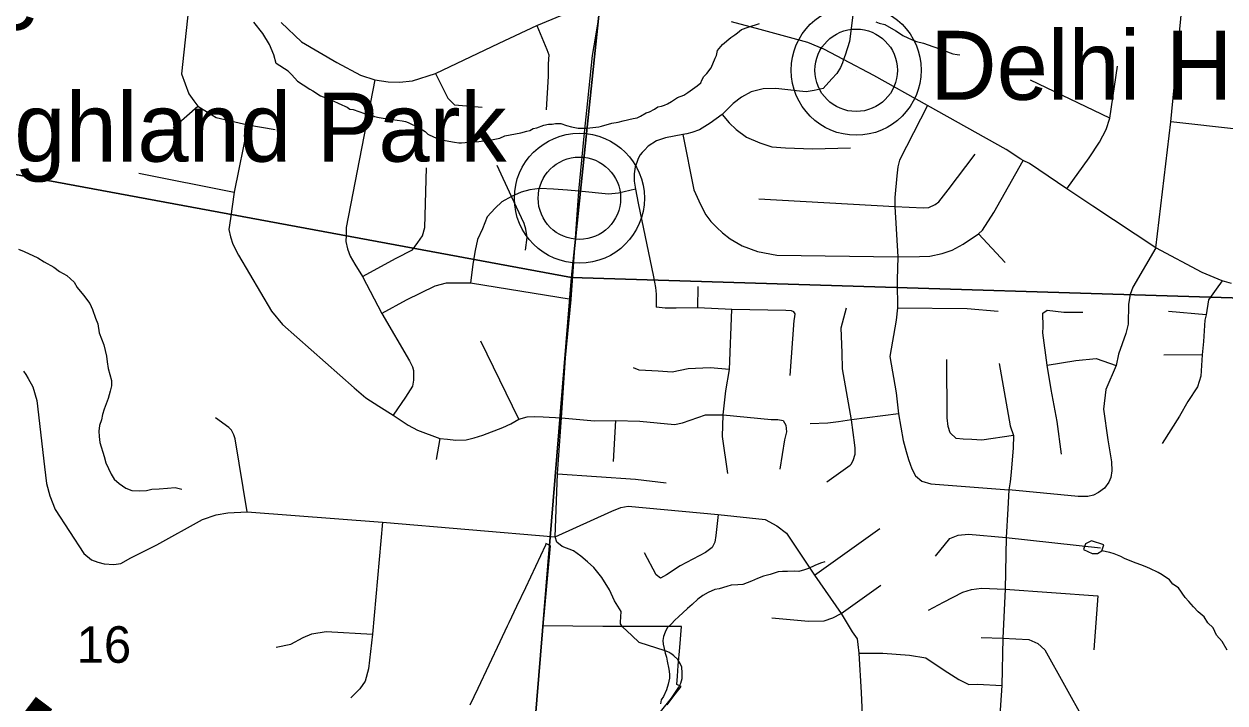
# Model space of a CAD drawing. Extents: x 0 to 43.4, y -8.1 to 22.
# Drawn here: x 6.917 to 8.292, y 14.72 to 15.497 of the extents above; entities that cross this region are included whole.
import ezdxf

# ---------------------------------------------------------------- set-up
doc = ezdxf.new("R2010")
doc.units = 0
for name, color, linetype in [('GM_X_Corporation', 7, 'Continuous'), ('GM_X_County_Road', 7, 'Continuous'), ('GM_X_County_Text', 7, 'Continuous'), ('GM_X_Minor_River', 7, 'Continuous'), ('GM_X_Section_Text', 7, 'Continuous'), ('GM_X_Township_Road', 7, 'Continuous'), ('GM_X_Unincorporated', 7, 'Continuous'), ('GM_X_Unincorporated_Location', 7, 'Continuous'), ('GM_X_Unincorporated_Text', 7, 'Continuous')]:
    doc.layers.add(name, color=color, linetype=linetype)

msp = doc.modelspace()

# ---------------------------------------------------------------- linework, layer by layer
at = {"layer": 'GM_X_Corporation'}
for points in [[(7.6501, 16.228), (7.5438, 15.2065), (6.5194, 15.3962), (6.6267, 16.4119)], [(8.6363, 16.199), (8.5356, 15.1762), (7.5438, 15.2065), (7.6501, 16.228)]]:
    msp.add_lwpolyline(points, close=True, dxfattribs=at)
for points in [[(6.5319, 14.7095), (6.5179, 14.7231), (6.5071, 14.7339), (6.4952, 14.7437), (6.48, 14.7554), (6.4748, 14.7597), (6.4674, 14.7675), (6.4608, 14.776), (6.4541, 14.7814), (6.5194, 15.3962), (7.5438, 15.2065), (7.4624, 14.2166)], [(7.4624, 14.2166), (7.5438, 15.2065), (8.5356, 15.1762), (8.4333, 14.2338)], [(7.6535, 14.7176), (7.6626, 14.7296), (7.6694, 14.7386), (7.6643, 14.7409), (7.6651, 14.7502), (7.6661, 14.7626), (7.6677, 14.7832), (7.6696, 14.807), (7.6426, 14.8071), (7.6251, 14.8073), (7.6212, 14.8072), (7.6046, 14.8073), (7.5905, 14.8073), (7.5867, 14.8073), (7.5797, 14.8073), (7.5452, 14.8076), (7.5113, 14.808), (7.5128, 14.8238), (7.5197, 14.8995), (7.5173, 14.9006), (7.5143, 14.9021), (7.5141, 14.9004), (7.491, 14.8516), (7.4809, 14.8302), (7.472, 14.8114), (7.4703, 14.8077), (7.4618, 14.7897), (7.4364, 14.7361), (7.4274, 14.717)]]:
    msp.add_lwpolyline(points, dxfattribs=at)
at = {"layer": 'GM_X_County_Road'}
msp.add_line((7.5696, 15.4718), (7.579, 15.5267), dxfattribs=at)
for points in [[(8.2129, 15.2407), (8.2301, 15.3849), (8.2507, 15.5974)], [(7.2112, 15.4986), (7.2347, 15.4766), (7.2749, 15.4527), (7.3022, 15.4383), (7.3186, 15.433), (7.334, 15.4307), (7.3468, 15.4303), (7.3616, 15.4317), (7.3881, 15.4404), (7.461, 15.475), (7.5042, 15.4951), (7.5327, 15.5069)], [(8.2993, 15.2), (8.2887, 15.203), (8.266, 15.2125), (8.2129, 15.2407), (8.1406, 15.2884), (8.1111, 15.3081), (8.0681, 15.337), (8.0609, 15.3408), (8.0584, 15.3421), (8.0413, 15.3532), (7.9514, 15.4035), (7.8898, 15.438), (7.8553, 15.4561), (7.8327, 15.468), (7.8263, 15.4708), (7.8143, 15.4757), (7.7598, 15.4907), (7.7271, 15.4992)], [(7.5613, 15.398), (7.5677, 15.4608), (7.5696, 15.4718)], [(7.5251, 14.9099), (7.5277, 14.9821), (7.5323, 15.0459), (7.537, 15.1149), (7.5435, 15.1815), (7.5523, 15.3057), (7.5583, 15.3686), (7.5598, 15.3832), (7.5613, 15.398)], [(7.5998, 14.8123), (7.6008, 14.8243), (7.593, 14.8364), (7.5873, 14.8492), (7.5786, 14.8632), (7.5694, 14.8746), (7.5622, 14.8812), (7.5544, 14.8878), (7.5461, 14.8937), (7.5332, 14.8986), (7.5268, 14.9037), (7.5251, 14.9099)], [(7.6568, 14.7767), (7.656, 14.7773), (7.6512, 14.7792), (7.6214, 14.7888), (7.6129, 14.7967), (7.6021, 14.8068), (7.5997, 14.8103), (7.5998, 14.8123)], [(7.6457, 14.7095), (7.6584, 14.7252), (7.6667, 14.7379), (7.6688, 14.7424), (7.6704, 14.7477), (7.6706, 14.7543), (7.67, 14.7606), (7.6683, 14.7649), (7.6656, 14.7694), (7.6611, 14.7736), (7.6586, 14.7755), (7.6568, 14.7767)]]:
    msp.add_lwpolyline(points, dxfattribs=at)
at = {"layer": 'GM_X_Minor_River'}
for points in [[(7.2194, 15.4427), (7.2056, 15.4516), (7.2028, 15.4615), (7.1978, 15.4734), (7.1905, 15.4861), (7.1802, 15.4989)], [(7.2194, 15.4427), (7.2234, 15.4387), (7.2301, 15.4313), (7.2364, 15.4273), (7.2443, 15.4222), (7.2477, 15.4205), (7.2563, 15.4146), (7.2676, 15.4105), (7.2807, 15.4044), (7.2841, 15.4028), (7.2871, 15.4015), (7.2901, 15.3995), (7.2939, 15.3991), (7.3067, 15.3945), (7.315, 15.3924), (7.3184, 15.3911), (7.3237, 15.3898), (7.3327, 15.3884), (7.3498, 15.3861), (7.3536, 15.3852), (7.3566, 15.384), (7.3686, 15.3783), (7.3731, 15.3759), (7.3761, 15.3739), (7.3794, 15.3708), (7.3866, 15.3675), (7.3926, 15.3651), (7.399, 15.3637), (7.41, 15.3615), (7.4149, 15.361), (7.4179, 15.3609), (7.4263, 15.3615), (7.4378, 15.3623), (7.4484, 15.3639), (7.4542, 15.3645), (7.4618, 15.3662), (7.4676, 15.3687), (7.4856, 15.3724), (7.4925, 15.3741), (7.4959, 15.3751), (7.4998, 15.3773), (7.504, 15.378), (7.512, 15.3812), (7.5174, 15.3821), (7.5216, 15.3824), (7.5254, 15.3831), (7.5315, 15.3829), (7.5379, 15.3808), (7.5439, 15.3791), (7.5515, 15.3778), (7.5614, 15.3775), (7.5751, 15.379), (7.5782, 15.3801), (7.5901, 15.3832), (7.5973, 15.3845), (7.6031, 15.3862), (7.6145, 15.3886), (7.6191, 15.3896), (7.6226, 15.3914), (7.6292, 15.395), (7.633, 15.3964), (7.6388, 15.3993), (7.6427, 15.4019), (7.6469, 15.4029), (7.6503, 15.404), (7.6538, 15.4054), (7.6581, 15.4083), (7.665, 15.4127), (7.6723, 15.4155), (7.677, 15.4184), (7.6878, 15.4261), (7.6917, 15.4295), (7.6929, 15.4325), (7.6953, 15.4366), (7.6989, 15.4403), (7.7036, 15.4466), (7.7081, 15.4576), (7.7097, 15.461), (7.711, 15.4666), (7.7165, 15.4733), (7.7262, 15.4814), (7.7308, 15.4844), (7.7339, 15.4866), (7.7386, 15.4906), (7.7459, 15.4931), (7.759, 15.4973)], [(7.8921, 15.4993), (7.8959, 15.498), (7.9027, 15.4963), (7.915, 15.4891), (7.9195, 15.4863), (7.9233, 15.4839), (7.9338, 15.4787), (7.9387, 15.477), (7.947, 15.4749), (7.9575, 15.4712), (7.9673, 15.4675), (7.9775, 15.4638), (7.9805, 15.4629), (7.9854, 15.462), (7.9884, 15.4615)], [(6.9105, 15.2392), (6.9169, 15.2364), (6.9329, 15.2293), (6.94, 15.2246), (6.951, 15.2187), (6.9574, 15.2137), (6.9661, 15.2089), (6.9743, 15.2012)], [(6.9743, 15.2012), (6.9777, 15.1951), (6.9852, 15.1866), (6.9922, 15.1769), (6.9955, 15.17), (6.9988, 15.1601), (7.0014, 15.1536), (7.0031, 15.1433), (7.0082, 15.1295), (7.0114, 15.1165), (7.012, 15.1101), (7.0134, 15.1024), (7.017, 15.0887), (7.0172, 15.0826), (7.0156, 15.0765), (7.0132, 15.0682), (7.0111, 15.0622), (7.0087, 15.0558), (7.0067, 15.0497), (7.0055, 15.0437), (7.0034, 15.0372), (7.0026, 15.0308), (7.0028, 15.0247), (7.0038, 15.0178), (7.0085, 15.0018), (7.0107, 14.9945), (7.0166, 14.9815), (7.0203, 14.9757), (7.0259, 14.9707), (7.0334, 14.9656), (7.0403, 14.9628), (7.0487, 14.9623), (7.0571, 14.9629), (7.0632, 14.9643), (7.0716, 14.9649), (7.0812, 14.9655), (7.09, 14.9661), (7.0976, 14.9645)], [(8.151, 14.8937), (8.1533, 14.9008), (8.139, 14.9053), (8.1324, 14.9017), (8.13, 14.8953), (8.1398, 14.8909), (8.1461, 14.8908)], [(8.1461, 14.8908), (8.151, 14.8937)], [(8.2944, 14.7801), (8.2889, 14.7901), (8.2823, 14.7972), (8.2783, 14.8057), (8.2724, 14.8112), (8.268, 14.8181), (8.2613, 14.824), (8.2558, 14.8295), (8.2506, 14.8357), (8.2466, 14.8404), (8.2389, 14.8513), (8.2322, 14.8557), (8.2285, 14.8607), (8.2199, 14.8663), (8.2154, 14.8691), (8.206, 14.8735), (8.2008, 14.876), (8.1955, 14.8777), (8.1902, 14.8797), (8.1853, 14.8817), (8.177, 14.885), (8.1729, 14.8874), (8.165, 14.8903), (8.1601, 14.892), (8.151, 14.8937)], [(7.8339, 14.8813), (7.8289, 14.8795), (7.8224, 14.877), (7.8151, 14.8734), (7.8105, 14.872), (7.804, 14.8703), (7.799, 14.8704), (7.791, 14.8703), (7.7853, 14.8701), (7.7804, 14.8698), (7.7712, 14.8666), (7.7635, 14.8646), (7.7566, 14.8621), (7.75, 14.8592), (7.745, 14.8571), (7.74, 14.8553), (7.7343, 14.8547), (7.7267, 14.8546), (7.7217, 14.8528), (7.7129, 14.8504), (7.7079, 14.8494), (7.7002, 14.8462), (7.6941, 14.8425), (7.6886, 14.8385), (7.682, 14.8322), (7.6765, 14.8278), (7.6664, 14.8182), (7.6621, 14.8145), (7.6582, 14.8104), (7.6535, 14.8056), (7.6511, 14.8007), (7.6491, 14.7958), (7.6482, 14.7912), (7.6488, 14.787), (7.6498, 14.7821), (7.6512, 14.7767), (7.6526, 14.7721), (7.6532, 14.7675), (7.6553, 14.7583), (7.6559, 14.7526), (7.6558, 14.748), (7.6544, 14.7412), (7.6524, 14.7348), (7.6491, 14.7272), (7.6463, 14.7231), (7.6455, 14.7186)]]:
    msp.add_lwpolyline(points, dxfattribs=at)
at = {"layer": 'GM_X_Township_Road'}
for p, q in [((8.1603, 15.3892), (8.0692, 15.4325)), ((7.0878, 15.3782), (7.116, 15.4029)), ((8.3085, 15.3762), (8.2301, 15.3849)), ((7.0484, 15.3262), (7.1577, 15.3043)), ((8.0098, 15.2568), (8.0402, 15.224)), ((7.6883, 15.172), (7.6887, 15.1964)), ((8.2706, 15.1638), (8.2275, 15.1678)), ((7.4835, 15.0446), (7.4401, 15.1338)), ((8.266, 15.1183), (8.222, 15.1179)), ((7.5943, 15.0428), (7.5913, 14.9961)), ((7.3929, 15.0223), (7.3887, 14.9982)), ((7.8221, 14.8661), (7.8969, 14.9192))]:
    msp.add_line(p, q, dxfattribs=at)
for points in [[(7.8591, 15.5841), (7.866, 15.5407), (7.8669, 15.516), (7.8621, 15.4767), (7.8573, 15.4611), (7.8553, 15.4561)], [(7.1116, 15.536), (7.1054, 15.5141), (7.0972, 15.4397), (7.1057, 15.417), (7.1114, 15.4091), (7.116, 15.4029), (7.1269, 15.396), (7.137, 15.3899), (7.1733, 15.3814), (7.2043, 15.3762)], [(7.5042, 15.4951), (7.5157, 15.4678), (7.518, 15.4614), (7.5172, 15.4513), (7.5172, 15.4372), (7.5146, 15.3986)], [(7.8553, 15.4561), (7.854, 15.4526), (7.8518, 15.447), (7.8476, 15.4404), (7.842, 15.434), (7.8319, 15.4232), (7.8218, 15.4207), (7.8126, 15.4191), (7.8048, 15.42), (7.7949, 15.421), (7.7777, 15.4229), (7.7632, 15.4226), (7.7495, 15.4191), (7.7386, 15.4133), (7.729, 15.4059), (7.7161, 15.3933), (7.7024, 15.3834), (7.6902, 15.3758), (7.6814, 15.3726), (7.676, 15.3712), (7.6712, 15.3703), (7.6513, 15.3666), (7.6411, 15.3633), (7.6314, 15.3569), (7.6274, 15.3526)], [(8.1111, 15.3081), (8.1364, 15.3438), (8.1484, 15.3615), (8.1559, 15.376), (8.1603, 15.3892), (8.169, 15.4487)], [(7.3186, 15.433), (7.2856, 15.2639), (7.2857, 15.2551), (7.2855, 15.2479), (7.2872, 15.2394), (7.2904, 15.2312), (7.2957, 15.2218), (7.3043, 15.2077), (7.3267, 15.1654), (7.3582, 15.1113), (7.3619, 15.1045), (7.3628, 15.1003), (7.3627, 15.0956), (7.3628, 15.0892), (7.3616, 15.0821), (7.3538, 15.0698), (7.3397, 15.049)], [(7.3881, 15.4404), (7.4023, 15.412), (7.4098, 15.4045), (7.4415, 15.4017)], [(7.9514, 15.4035), (7.9194, 15.3409), (7.9173, 15.3334), (7.9163, 15.3231), (7.9141, 15.2982), (7.9139, 15.2881), (7.9176, 15.2304), (7.9168, 15.204), (7.9168, 15.2011)], [(7.7161, 15.3933), (7.7244, 15.3838), (7.7325, 15.376), (7.7443, 15.3675), (7.7594, 15.361), (7.773, 15.3564), (7.7889, 15.355), (7.8199, 15.354), (7.8634, 15.3553)], [(7.1733, 15.3814), (7.1577, 15.3043), (7.1533, 15.2744)], [(7.6712, 15.3703), (7.6838, 15.3072), (7.6914, 15.2901), (7.6976, 15.2786), (7.7032, 15.2709), (7.7102, 15.2639), (7.7167, 15.2577), (7.7255, 15.2509), (7.7392, 15.2429), (7.7567, 15.2366), (7.7787, 15.2323), (7.9176, 15.2304), (7.9422, 15.2308), (7.9539, 15.231), (7.9683, 15.2343), (7.9798, 15.2381), (7.9923, 15.2448), (8.0098, 15.2568), (8.0142, 15.261), (8.0272, 15.2812), (8.0609, 15.3408)], [(7.6274, 15.3526), (7.6247, 15.3497), (7.6223, 15.347), (7.6202, 15.343), (7.6185, 15.3384), (7.6167, 15.3333), (7.6155, 15.3255), (7.6157, 15.3169), (7.617, 15.3079)], [(7.7584, 15.2966), (7.9139, 15.2881), (7.9467, 15.2863), (7.9528, 15.2869), (7.9601, 15.2901), (7.9643, 15.2934), (7.9749, 15.3072), (8.006, 15.3479)], [(7.4911, 15.238), (7.4929, 15.2526), (7.4916, 15.262), (7.4895, 15.2686), (7.4749, 15.2995), (7.4585, 15.3349)], [(7.3043, 15.2077), (7.3429, 15.2289), (7.3617, 15.2383), (7.3679, 15.2469), (7.3731, 15.2545), (7.376, 15.2641), (7.3776, 15.3321)], [(7.617, 15.3079), (7.5976, 15.3034), (7.5861, 15.3022), (7.5523, 15.3057), (7.5393, 15.3068), (7.5231, 15.3079), (7.5075, 15.3086), (7.4959, 15.3072), (7.4863, 15.3043), (7.4749, 15.2995), (7.4642, 15.2933), (7.4562, 15.2862), (7.4473, 15.276), (7.4417, 15.2625), (7.4361, 15.2501), (7.4336, 15.2376), (7.4308, 15.222), (7.4283, 15.2003)], [(7.617, 15.3079), (7.6202, 15.2919), (7.6376, 15.2073), (7.6399, 15.1952), (7.6406, 15.1875), (7.6406, 15.1726)], [(7.1533, 15.2744), (7.1515, 15.2615), (7.1532, 15.2531), (7.1559, 15.2449), (7.1625, 15.2321), (7.2004, 15.168), (7.213, 15.1527), (7.295, 15.0803), (7.3082, 15.0691), (7.3232, 15.0595), (7.3397, 15.049), (7.3566, 15.0376), (7.3673, 15.0318), (7.3929, 15.0223), (7.4018, 15.0218), (7.4112, 15.0204), (7.423, 15.0209), (7.4324, 15.023), (7.4422, 15.0261), (7.4651, 15.035), (7.4744, 15.0392), (7.4835, 15.0446)], [(8.2129, 15.2407), (8.1866, 15.1958), (8.1834, 15.1871), (8.1816, 15.1762), (8.1813, 15.1531), (8.1784, 15.1425), (8.1702, 15.1188), (8.1675, 15.1061), (8.1555, 15.0785), (8.1529, 15.0558), (8.158, 15.0208), (8.162, 14.9957), (8.1623, 14.9855), (8.1612, 14.9779), (8.1589, 14.9724), (8.154, 14.9656), (8.147, 14.9607), (8.1413, 14.9575), (8.1349, 14.9559), (8.1239, 14.9561), (8.0445, 14.9637)], [(7.5435, 15.1815), (7.4283, 15.2003), (7.4102, 15.2001), (7.4004, 15.2001), (7.3874, 15.1969), (7.3546, 15.1809), (7.3267, 15.1654)], [(7.9168, 15.2011), (7.9171, 15.1721), (7.9154, 15.1578), (7.9082, 15.1162), (7.9157, 15.0747), (7.9175, 15.0573), (7.9182, 15.0505), (7.9237, 15.0201), (7.927, 15.0074), (7.9296, 14.9983), (7.9334, 14.9877), (7.9376, 14.9796), (7.9448, 14.9735), (7.9553, 14.9703), (7.9752, 14.969), (8.0445, 14.9637)], [(8.2887, 15.203), (8.2732, 15.1811), (8.2706, 15.1638), (8.2689, 15.158), (8.2675, 15.1334), (8.266, 15.1183), (8.2645, 15.0937), (8.2606, 15.0816), (8.2494, 15.0649), (8.2399, 15.0479), (8.2201, 15.0167)], [(7.7941, 15.0944), (7.7989, 15.1575), (7.7996, 15.1617), (7.7999, 15.1651), (7.7984, 15.1674), (7.7956, 15.1687), (7.7893, 15.169), (7.7272, 15.17), (7.6883, 15.172), (7.6635, 15.1714), (7.6511, 15.1714), (7.6406, 15.1726)], [(7.7226, 14.9824), (7.7167, 15.0245), (7.7176, 15.0493), (7.7203, 15.0771), (7.7247, 15.1013), (7.7272, 15.17)], [(7.8361, 14.9728), (7.863, 14.992), (7.8639, 14.993), (7.8663, 14.9971), (7.8684, 15.0046), (7.8687, 15.0076), (7.8687, 15.0115), (7.8683, 15.0149), (7.8643, 15.0437), (7.8564, 15.0893), (7.8541, 15.1022), (7.8537, 15.1204), (7.8526, 15.1491), (7.8587, 15.1718)], [(7.9171, 15.1721), (7.997, 15.1713), (8.0322, 15.1682)], [(8.105, 15.0045), (8.0999, 15.0418), (8.0931, 15.0785), (8.0885, 15.1062), (8.0834, 15.1435), (8.0839, 15.1503), (8.0836, 15.166), (8.0885, 15.1694), (8.1075, 15.1671), (8.1294, 15.1671)], [(8.0498, 15.0258), (8.0136, 15.0206), (8.0021, 15.0212), (7.9924, 15.0218), (7.9843, 15.0225), (7.9773, 15.0287), (7.9749, 15.036), (7.974, 15.0459), (7.9735, 15.113)], [(8.0885, 15.1062), (8.1211, 15.1115), (8.1445, 15.1141), (8.1675, 15.1061)], [(6.9163, 15.0994), (6.9189, 15.0956), (6.9218, 15.0911), (6.9271, 15.0814), (6.9315, 15.066), (6.9402, 14.9899), (6.9428, 14.971), (6.9466, 14.9568), (6.9527, 14.941), (6.9854, 14.8909), (6.9942, 14.8833), (7.0016, 14.8808), (7.0086, 14.8788), (7.0198, 14.8782), (7.0276, 14.8794), (7.0391, 14.8858), (7.0691, 14.9006), (7.1214, 14.9295), (7.1371, 14.9349), (7.1504, 14.9372), (7.1725, 14.9383), (7.3275, 14.9266), (7.5251, 14.9099)], [(7.7247, 15.1013), (7.7026, 15.1034), (7.6774, 15.1022), (7.6591, 15.0983), (7.6431, 15.0996), (7.6214, 15.1006), (7.6147, 15.1031)], [(8.0336, 15.1084), (8.0462, 15.0367), (8.0498, 15.0258), (8.0494, 15.0118), (8.0471, 14.9839), (8.046, 14.9726), (8.0445, 14.9637), (8.0432, 14.9418)], [(7.1725, 14.9383), (7.1587, 15.022), (7.1573, 15.0266), (7.1544, 15.0319), (7.1514, 15.035), (7.1361, 15.046)], [(7.4835, 15.0446), (7.4932, 15.0471), (7.5011, 15.0474), (7.5114, 15.0471), (7.5323, 15.0459)], [(7.5323, 15.0459), (7.5534, 15.0442), (7.5702, 15.0426), (7.5943, 15.0428), (7.6221, 15.0421), (7.6616, 15.0385), (7.6709, 15.0402), (7.6972, 15.0495), (7.7176, 15.0493), (7.7723, 15.044), (7.7802, 15.0442), (7.7861, 15.0429), (7.7893, 15.0376), (7.7899, 15.03), (7.7878, 15.0207), (7.7823, 14.9871)], [(7.9182, 15.0505), (7.8643, 15.0437), (7.8496, 15.0415), (7.8373, 15.0399), (7.817, 15.039)], [(7.5277, 14.9821), (7.6172, 14.9758), (7.6522, 14.9716)], [(7.5251, 14.9099), (7.59, 14.9393), (7.6002, 14.9435), (7.6085, 14.945), (7.7118, 14.9353), (7.7654, 14.9296), (7.779, 14.9225), (7.79, 14.9141), (7.8221, 14.8661), (7.8524, 14.8222), (7.8651, 14.8012), (7.8708, 14.793), (7.8717, 14.7866), (7.8729, 14.7768), (7.8755, 14.7315), (7.8774, 14.6888), (7.8673, 14.5792)], [(7.7118, 14.9353), (7.709, 14.9112), (7.7079, 14.9036), (7.7048, 14.8977), (7.6971, 14.8918), (7.6681, 14.8767), (7.6524, 14.8663), (7.6456, 14.8625), (7.6409, 14.8664), (7.6275, 14.8916)], [(8.0432, 14.9418), (8.0414, 14.909), (8.0403, 14.85), (8.0376, 14.7938), (8.0364, 14.7395), (8.0337, 14.7004), (8.0354, 14.6939), (8.0397, 14.687), (8.0463, 14.6793), (8.068, 14.654), (8.091, 14.6268), (8.1014, 14.6144), (8.1182, 14.6041), (8.1275, 14.5986), (8.1459, 14.5931)], [(7.3275, 14.9266), (7.3158, 14.7983), (7.3115, 14.7586), (7.3074, 14.7446), (7.3015, 14.736), (7.2912, 14.7256)], [(7.9605, 14.8878), (7.9771, 14.9079), (7.9866, 14.9117), (7.9983, 14.9128), (8.0414, 14.909), (8.1493, 14.8973)], [(7.7733, 14.8169), (7.8153, 14.8131), (7.8331, 14.8135), (7.843, 14.8169), (7.8524, 14.8222), (7.8978, 14.8543)], [(7.9525, 14.8258), (7.9699, 14.835), (7.9917, 14.8464), (8.0019, 14.8496), (8.0134, 14.8511), (8.0403, 14.85), (8.1466, 14.8424), (8.1418, 14.7806)], [(7.2057, 14.7834), (7.2224, 14.7868), (7.2364, 14.7947), (7.2463, 14.7989), (7.2628, 14.8014), (7.3158, 14.7983)], [(8.0127, 14.7947), (8.0376, 14.7938), (8.0675, 14.7923), (8.0779, 14.7877), (8.0857, 14.7805), (8.1309, 14.6996), (8.1491, 14.6693)], [(7.8729, 14.7768), (7.9001, 14.7768), (7.9308, 14.7745), (7.9495, 14.7713), (7.9705, 14.7573), (7.9871, 14.7465), (7.9989, 14.7406), (8.0087, 14.741), (8.0364, 14.7395)]]:
    msp.add_lwpolyline(points, dxfattribs=at)
at = {"layer": 'GM_X_Unincorporated'}
for centre, radius in [((7.8697, 15.4439), 0.0744), ((7.8697, 15.4439), 0.0472), ((7.5528, 15.2974), 0.0744), ((7.5528, 15.2974), 0.0472)]:
    msp.add_circle(centre, radius, dxfattribs=at)
at = {"layer": 'GM_X_Unincorporated_Location'}
for p, q in [((7.8697, 15.4439), (7.8697, 15.4439)), ((7.5528, 15.2974), (7.5528, 15.2974))]:
    msp.add_line(p, q, dxfattribs=at)

# ---------------------------------------------------------------- texts
at = {"layer": 'GM_X_County_Text'}
msp.add_text('U', height=0.1894, rotation=322.8562, dxfattribs=at).set_placement((6.8005, 14.5875))
at = {"layer": 'GM_X_Section_Text'}
msp.add_text('16', height=0.04186, rotation=0, dxfattribs=at).set_placement((6.9773, 14.7656))
at = {"layer": 'GM_X_Unincorporated_Text'}
for s, height, p in [('Sunaire', 0.07898, (6.5702, 15.4901)), ('Delhi Hills', 0.078977, (7.9543, 15.4101)), ('Highland Park', 0.078977, (6.806, 15.3393))]:
    msp.add_text(s, height=height, rotation=0, dxfattribs=at).set_placement(p)

doc.saveas('drawing.dxf')
